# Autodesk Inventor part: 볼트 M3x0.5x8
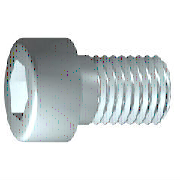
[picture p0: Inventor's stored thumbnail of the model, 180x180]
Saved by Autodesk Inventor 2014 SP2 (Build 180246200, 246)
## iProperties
IsCustomPart: 1
Company: 한국ATC센터
Created: 2015-12
Part Number: 볼트 M3x0.5x8
Material: 스테인리스강
Description: 6각머리 태핑 나사
Document SubType Name: Modeling
Standard: KS B 1003
Designer: mdu
Standards Organization: KS
Language: ko-KR
Size Designation: M 4 x 12
Categories: <MemberInstance><Categories><Category DisplayName="조임쇠" InternalName="e4da775c-781d-43d5-af7c-5136215cf5a6" Mnemonic="FSTN"><Category DisplayName="볼트" InternalN
Density: 8.08 g/cm^3
Mass: 1.41278 g
Surface Area: 2.58399 cm^2
Volume: 0.174849 cm^3
Appearance: 반광택
Author: mdu
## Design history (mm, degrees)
sketch "스케치1"
  geometry: L1 (-0.867, 0)-(16, 0); L2 (16, 0)-(16, 1.5); L3 (16, 1.5)-(1.25, 1.5); L4 (1.25, 1.5)-(0.943, 1.5); L5 (0.943, 1.5)-(0, 1.5); L6 (0, 1.5)-(0, 2.75); L7 (0, 2.75)-(-3, 2.75); L8 (-3, 2.75)-(-3, 1.443); L9 (-3, 1.443)-(-1.7, 1.443); L10 (-1.7, 1.443)-(-0.867, 0); L11 (-6.8, 0)-(19.8, 0) reference; L12 (0, -0.55)-(0, 3.3) reference; L13 (1.25, 1.5)-(0, 1.5)
  constraints: 22 end point, 6 parallel, 2 collinear, 2 perpendicular, 1 horizontal, 1 point on line
  dimensions: "d1" = 14.75 distance from line of L3.end L2 (= GEL); "d2" = 0.30683 distance of L4.end L3.end (computed from GAL); "d3" = 3 distance between parallel lines of L8 L6 (= KOH); "d4" = 1.3 distance of L8.end L9.end (= INTI); "d5" = 60 deg angle of L10 L1; "d6" = 3 diameter of L3 L1 (= GD); "d7" = 3 diameter of L5 L1 (= BDM); "d8" = 2.88675 diameter of L9 L1 (= 1.1547 x SW); "d9" = 5.5 diameter of L7 L1 (= KOD); "d26" = 16 distance between parallel lines of L12 L2 (= NLG)
revolve "본체" sketch "스케치1" stored, may be unused: angle "d10" = 90 deg
sketch "스케치2"
  geometry: L1 (0, -3.85)-(0, 3.85) reference; L2 (-3.85, 0)-(3.85, 0) reference; L3 (1.443, 0)-(0.722, -1.25); L4 (0.722, -1.25)-(-0.722, -1.25); L5 (-0.722, -1.25)-(-1.443, 0); L6 (-1.443, 0)-(-0.722, 1.25); L7 (-0.722, 1.25)-(0.722, 1.25); L8 (0.722, 1.25)-(1.443, 0); 2 further points
  constraints: 12 end point, 1 coincident, 1 horizontal alignment, 1 point on line, 12 other
extrude "슬롯" join sketch "스케치2" stored distance "d11" = 10; taper "d12" = 0 deg
workplane "Work Plane1"
fillet "Fillet2" dims "d30" = 0.1 (= R)
body "Solid1"
fillet "모깎기1" dims "d17" = 0.3 (= RR)
feature "스레드" dims "d13" = 14.75 (= GEL), "d14" = 0
chamfer "모따기1" distance "d15" = 0.30673 (= -0.5 x SPD + 0.5 x GD); stored, may be unused: second distance "d16" = 0.30673 (= GUL), angle "d27" = 45 deg
other parameters: "GD" = 3 (= NND) [user parameter; used in 2 equation terms], "NLG" = 16 [user parameter; used in 1 equation term], "GEL" = 14.75 [user parameter; used in 2 equation terms], "KOD" = 5.5 [user parameter; used in 1 equation term], "KOH" = 3 [user parameter; used in 1 equation term], "INTI" = 1.3 [user parameter; used in 1 equation term], "GAL" = 0.30673 (= 0.61345 x PTC) [user parameter; used in 1 equation term], "GUL" = 0.30673 (= 0.61345 x PTC) [user parameter; used in 1 equation term], "BDM" = 3 (= NND) [user parameter; used in 1 equation term], "SW" = 2.5 [user parameter; used in 2 equation terms], "RR" = 0.3 [user parameter; used in 1 equation term], "SPD" = 2.38655 (= NND - 1.2269 x PTC) [user parameter; used in 1 equation term], "d19" = 0, "d28" = 0, "d29" = 0, "R" = 0.1 [user parameter; used in 1 equation term], "PHH" = 0.1 [user parameter], "GD1" = 2.38655 (= THREADDIA - 1.2269 x PTC) [user parameter], "THREADDIA" = 3 [user parameter; used in 1 equation term], "FAWI" = 45 deg [user parameter], "PTC" = 0.5 [user parameter; used in 5 equation terms], "NND" = 3 [user parameter; used in 3 equation terms], "TOA" = 30 deg [user parameter], "E0" = 2.8875 (= 1.155 x SW) [user parameter]
